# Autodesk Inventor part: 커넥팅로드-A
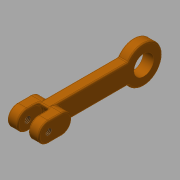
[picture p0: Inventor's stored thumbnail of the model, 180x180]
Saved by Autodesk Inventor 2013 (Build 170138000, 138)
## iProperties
Created: 2018-01
Part Number: 커넥팅로드-A
Material: 알루미늄 6061
Document SubType Name: Modeling
Designer: mduedu
Density: 2.71 g/cm^3
Mass: 5.11805 g
Surface Area: 16.3537 cm^2
Volume: 1.88858 cm^3
Author: mduedu
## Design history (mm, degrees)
sketch "스케치1"
  geometry: L1 (0, 0)-(0, 40); L2 (3.75, 40)-(3.75, 5.911); L3 (-3.75, 40)-(-3.75, 5.911); A1 r 7 centre (0, 0) between (3.75, 5.911) and (-3.75, 5.911); A2 r 3.75 centre (0, 40) between (3.75, 40) and (-3.75, 40); 1 further point
  constraints: 6 end point, 4 point on circle, 2 centre point, 2 coincident, 2 parallel, 2 tangent, 1 vertical
  dimensions: "d1" = 40 distance of L1.start L1.end; "d2" = 7.5 diameter of A2; "d3" = 14 diameter of A1
extrude "돌출1" new body sketch "스케치1" stored distance "d4" = 4; taper "d5" = 0 deg
sketch "스케치2"
  geometry: L1 (-3.75, 40)-(-3.75, 35); L2 (3.75, 40)-(3.75, 35); A1 r 3.75 centre (0, 40) between (3.75, 40) and (-3.75, 40) reference; A2 r 3.75 centre (0, 40) between (3.75, 40) and (-3.75, 40); A3 r 3.75 centre (0, 35) between (-3.75, 35) and (3.75, 35); 1 further point
  constraints: 4 end point, 4 point on circle, 2 centre point, 2 tangent, 1 coincident, 1 equal radius, 1 point on line, 1 vertical alignment
  dimensions: "d6" = 5 distance of A3.centre A1.centre
extrude "돌출2" join sketch "스케치2" stored distance "d7" = 12; taper "d8" = 0 deg
sketch "스케치3"
  geometry: L1 (3.75, 40)-(3.75, 38); L2 (-3.75, 40)-(-3.75, 38); A1 r 3.75 centre (0, 40) between (3.75, 40) and (-3.75, 40) reference; A2 r 3.75 centre (0, 40) between (3.75, 40) and (-3.75, 40); A3 r 3.75 centre (0, 38) between (-3.75, 38) and (3.75, 38); 1 further point
  constraints: 4 end point, 4 point on circle, 3 tangent, 2 centre point, 1 coincident, 1 equal radius, 1 parallel, 1 point on line
  dimensions: "d9" = 2 distance of A3.centre A1.centre
extrude "돌출3" cut sketch "스케치3" stored distance "d10" = 4; taper "d11" = 0 deg
fillet "모깎기5" dims "d16" = 0.5
fillet "모깎기6" dims "d17" = 0.5
fillet "모깎기7" dims "d18" = 0.5
fillet "모깎기8" dims "d19" = 0.5
hole "구멍1" diameter "d22" = 7.5; stored, may be unused: countersink angle "d26" = 90 deg, drill point angle "d28" = 118 deg; dims "d20" = 10, "d21" = 10, "d23" = 6, "d24" = 4, "d25" = 2, "d27" = 8
sketch "스케치4"
  geometry: A1 r 3.75 centre (40, 0) between (40, -3.75) and (40, 3.75) reference; 2 further points
  constraints: 1 coincident
sketch "스케치5"
  geometry: 1 further point
  constraints: 1 other
hole "구멍2" sketch "스케치5" at (40, 0) diameter "d29" = 2.459; stored, may be unused: countersink angle "d33" = 90 deg, drill point angle "d35" = 0 deg; dims "d30" = 6, "d31" = 4, "d32" = 2, "d34" = 8
sketch "스케치6"
  geometry: 1 further point
  constraints: 1 other
hole "구멍4" sketch "스케치6" at (-40, 0) diameter "d36" = 2.459; stored, may be unused: countersink angle "d40" = 90 deg, drill point angle "d42" = 0 deg; dims "d37" = 6, "d38" = 4, "d39" = 2, "d41" = 8
node "솔리드1"
